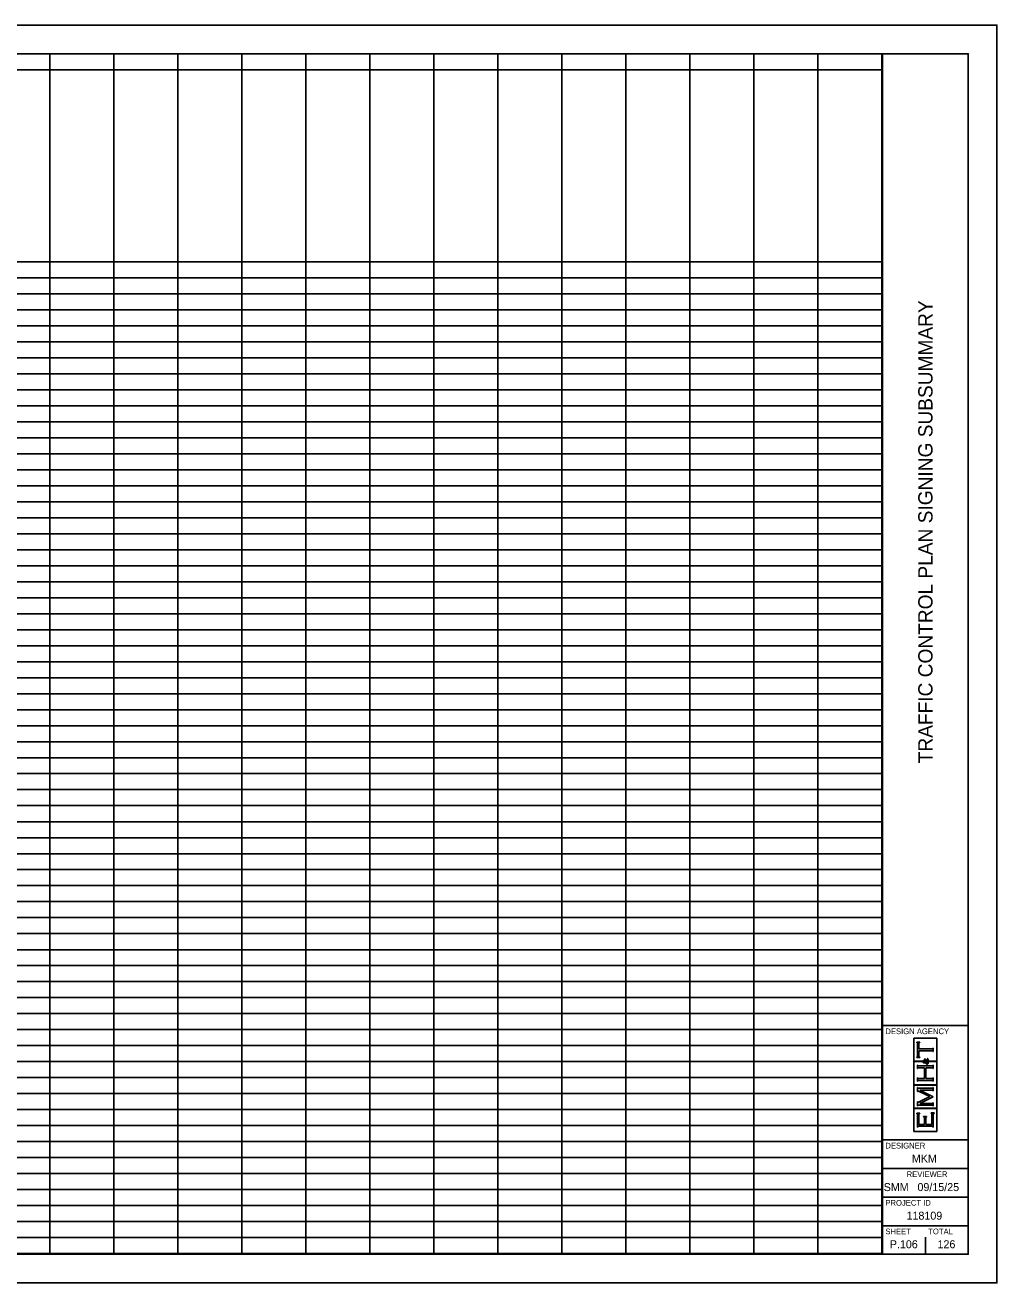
# Model space of a CAD drawing. Extents: x 0 to 34, y 0 to 22.
# Drawn here: x 17 to 34, y 0 to 22 of the extents above; entities that cross this region are included whole.
import ezdxf

# ---------------------------------------------------------------- set-up
doc = ezdxf.new("R2010")
doc.units = 0
for name, color, linetype in [('Default', 7, 'Continuous'), ('SH_Border', 7, 'Continuous'), ('SH_Cut_Line', 7, 'Continuous'), ('SH_Data', 7, 'Continuous')]:
    doc.layers.add(name, color=color, linetype=linetype)

msp = doc.modelspace()

# ---------------------------------------------------------------- linework, layer by layer
at = {"layer": 'Default'}
for p, q in [((1.5, 21.499), (31.985, 21.499)), ((17.434, 21.499), (17.434, 0.512)), ((18.553, 21.499), (18.553, 0.512)), ((19.673, 21.499), (19.673, 0.512)), ((20.792, 21.499), (20.792, 0.512)), ((21.911, 21.499), (21.911, 0.512)), ((23.031, 21.499), (23.031, 0.512)), ((24.15, 21.499), (24.15, 0.512)), ((25.269, 21.499), (25.269, 0.512)), ((26.389, 21.499), (26.389, 0.512)), ((27.508, 21.499), (27.508, 0.512)), ((28.627, 21.499), (28.627, 0.512)), ((29.747, 21.499), (29.747, 0.512)), ((30.866, 21.499), (30.866, 0.512)), ((31.985, 21.499), (31.985, 0.512)), ((10.718, 21.219), (31.985, 21.219)), ((10.718, 17.861), (31.985, 17.861)), ((1.5, 17.581), (31.985, 17.581)), ((1.5, 17.302), (31.985, 17.302)), ((1.5, 17.022), (31.985, 17.022)), ((1.5, 16.742), (31.985, 16.742)), ((1.5, 16.462), (31.985, 16.462)), ((1.5, 16.182), (31.985, 16.182)), ((1.5, 15.902), (31.985, 15.902)), ((1.5, 15.623), (31.985, 15.623)), ((1.5, 15.343), (31.985, 15.343)), ((1.5, 15.063), (31.985, 15.063)), ((1.5, 14.783), (31.985, 14.783)), ((1.5, 14.503), (31.985, 14.503)), ((1.5, 14.223), (31.985, 14.223)), ((1.5, 13.944), (31.985, 13.944)), ((1.5, 13.664), (31.985, 13.664)), ((1.5, 13.384), (31.985, 13.384)), ((1.5, 13.104), (31.985, 13.104)), ((1.5, 12.824), (31.985, 12.824)), ((1.5, 12.544), (31.985, 12.544)), ((1.5, 12.265), (31.985, 12.265)), ((1.5, 11.985), (31.985, 11.985)), ((1.5, 11.705), (31.985, 11.705)), ((1.5, 11.425), (31.985, 11.425)), ((1.5, 11.145), (31.985, 11.145)), ((1.5, 10.865), (31.985, 10.865)), ((1.5, 10.586), (31.985, 10.586)), ((1.5, 10.306), (31.985, 10.306)), ((1.5, 10.026), (31.985, 10.026)), ((1.5, 9.746), (31.985, 9.746)), ((1.5, 9.466), (31.985, 9.466)), ((1.5, 9.186), (31.985, 9.186)), ((1.5, 8.907), (31.985, 8.907)), ((1.5, 8.627), (31.985, 8.627)), ((1.5, 8.347), (31.985, 8.347)), ((1.5, 8.067), (31.985, 8.067)), ((1.5, 7.787), (31.985, 7.787)), ((1.5, 7.507), (31.985, 7.507)), ((1.5, 7.228), (31.985, 7.228)), ((1.5, 6.948), (31.985, 6.948)), ((1.5, 6.668), (31.985, 6.668)), ((1.5, 6.388), (31.985, 6.388)), ((1.5, 6.108), (31.985, 6.108)), ((1.5, 5.828), (31.985, 5.828)), ((1.5, 5.549), (31.985, 5.549)), ((1.5, 5.269), (31.985, 5.269)), ((1.5, 4.989), (31.985, 4.989)), ((1.5, 4.709), (31.985, 4.709)), ((1.5, 4.429), (31.985, 4.429)), ((1.5, 4.149), (31.985, 4.149)), ((1.5, 3.87), (31.985, 3.87)), ((1.5, 3.59), (31.985, 3.59)), ((1.5, 3.31), (31.985, 3.31)), ((1.5, 3.03), (31.985, 3.03)), ((1.5, 2.75), (31.985, 2.75)), ((1.5, 2.47), (31.985, 2.47)), ((1.5, 2.191), (31.985, 2.191)), ((1.5, 1.911), (31.985, 1.911)), ((1.5, 1.631), (31.985, 1.631)), ((1.5, 1.351), (31.985, 1.351)), ((1.5, 1.071), (31.985, 1.071)), ((1.5, 0.791), (31.985, 0.791)), ((1.5, 0.512), (31.985, 0.512))]:
    msp.add_line(p, q, dxfattribs=at)
at = {"layer": 'SH_Border'}
for p, q in [((32, 0.5), (32, 21.5)), ((32, 4.5), (33.5, 4.5)), ((32, 2.5), (33.5, 2.5)), ((32, 2), (33.5, 2)), ((32, 1.5), (33.5, 1.5)), ((32, 1), (33.5, 1))]:
    msp.add_line(p, q, dxfattribs=at)
msp.add_lwpolyline([(1.5, 21.5), (33.5, 21.5), (33.5, 0.5), (1.5, 0.5)], close=True, dxfattribs=at)
at = {"layer": 'SH_Cut_Line'}
msp.add_lwpolyline([(0, 0), (34, 0), (34, 22), (0, 22)], close=True, dxfattribs=at)
at = {"layer": 'SH_Data'}
for p, q in [((32.952, 4.279), (32.547, 4.279)), ((32.547, 4.279), (32.547, 3.875)), ((32.598, 4.204), (32.598, 4.211)), ((32.598, 4.211), (32.65, 4.211)), ((32.603, 4.203), (32.598, 4.204)), ((32.606, 4.201), (32.603, 4.203)), ((32.608, 4.199), (32.606, 4.201)), ((32.61, 4.196), (32.608, 4.199)), ((32.611, 4.192), (32.61, 4.196)), ((32.611, 4.187), (32.611, 4.192)), ((32.611, 3.968), (32.611, 4.187)), ((32.638, 4.196), (32.637, 4.192)), ((32.637, 4.192), (32.637, 4.187)), ((32.637, 4.187), (32.637, 4.093)), ((32.64, 4.199), (32.638, 4.196)), ((32.642, 4.201), (32.64, 4.199)), ((32.645, 4.203), (32.642, 4.201)), ((32.65, 4.204), (32.645, 4.203)), ((32.65, 4.211), (32.65, 4.204)), ((32.952, 3.875), (32.952, 4.279)), ((32.61, 3.958), (32.611, 3.962)), ((32.611, 3.962), (32.611, 3.968)), ((32.637, 4.093), (32.864, 4.093)), ((32.864, 4.061), (32.637, 4.061)), ((32.637, 4.061), (32.637, 3.968)), ((32.637, 3.968), (32.637, 3.962)), ((32.637, 3.962), (32.638, 3.958)), ((32.864, 4.093), (32.869, 4.093)), ((32.87, 4.061), (32.864, 4.061)), ((32.869, 4.093), (32.873, 4.094)), ((32.874, 4.06), (32.87, 4.061)), ((32.873, 4.094), (32.876, 4.096)), ((32.876, 4.059), (32.874, 4.06)), ((32.876, 4.096), (32.878, 4.097)), ((32.878, 4.057), (32.876, 4.059)), ((32.878, 4.097), (32.88, 4.101)), ((32.88, 4.053), (32.878, 4.057)), ((32.88, 4.101), (32.881, 4.106)), ((32.881, 4.048), (32.88, 4.053)), ((32.881, 4.106), (32.888, 4.106)), ((32.888, 4.048), (32.881, 4.048)), ((32.888, 4.106), (32.888, 4.048)), ((32.547, 3.875), (32.696, 3.875)), ((32.696, 3.869), (32.547, 3.869)), ((32.547, 3.869), (32.547, 3.465)), ((32.598, 3.95), (32.603, 3.951)), ((32.598, 3.944), (32.598, 3.95)), ((32.65, 3.944), (32.598, 3.944)), ((32.603, 3.951), (32.606, 3.953)), ((32.606, 3.953), (32.608, 3.955)), ((32.608, 3.955), (32.61, 3.958)), ((32.611, 3.749), (32.611, 3.807)), ((32.611, 3.807), (32.617, 3.807)), ((32.617, 3.749), (32.611, 3.749)), ((32.617, 3.807), (32.619, 3.802)), ((32.618, 3.754), (32.617, 3.749)), ((32.62, 3.758), (32.618, 3.754)), ((32.619, 3.802), (32.62, 3.798)), ((32.62, 3.798), (32.623, 3.797)), ((32.623, 3.76), (32.62, 3.758)), ((32.623, 3.797), (32.625, 3.795)), ((32.625, 3.761), (32.623, 3.76)), ((32.625, 3.795), (32.629, 3.794)), ((32.629, 3.762), (32.625, 3.761)), ((32.629, 3.794), (32.635, 3.794)), ((32.635, 3.762), (32.629, 3.762)), ((32.635, 3.794), (32.864, 3.794)), ((32.732, 3.762), (32.635, 3.762)), ((32.638, 3.958), (32.64, 3.955)), ((32.64, 3.955), (32.642, 3.953)), ((32.642, 3.953), (32.645, 3.951)), ((32.645, 3.951), (32.65, 3.95)), ((32.65, 3.95), (32.65, 3.944)), ((32.696, 3.875), (32.696, 3.869)), ((32.703, 3.879), (32.705, 3.883)), ((32.703, 3.873), (32.703, 3.879)), ((32.703, 3.868), (32.703, 3.873)), ((32.705, 3.863), (32.703, 3.868)), ((32.705, 3.883), (32.708, 3.887)), ((32.708, 3.858), (32.705, 3.863)), ((32.708, 3.887), (32.711, 3.89)), ((32.709, 3.879), (32.708, 3.876)), ((32.708, 3.876), (32.708, 3.873)), ((32.708, 3.873), (32.708, 3.869)), ((32.708, 3.869), (32.71, 3.866)), ((32.712, 3.853), (32.708, 3.858)), ((32.712, 3.881), (32.709, 3.879)), ((32.71, 3.866), (32.712, 3.864)), ((32.711, 3.89), (32.715, 3.892)), ((32.714, 3.883), (32.712, 3.881)), ((32.712, 3.864), (32.715, 3.862)), ((32.718, 3.85), (32.712, 3.853)), ((32.716, 3.884), (32.714, 3.883)), ((32.715, 3.892), (32.72, 3.892)), ((32.715, 3.862), (32.718, 3.861)), ((32.72, 3.884), (32.716, 3.884)), ((32.718, 3.861), (32.721, 3.861)), ((32.726, 3.85), (32.718, 3.85)), ((32.72, 3.892), (32.725, 3.892)), ((32.724, 3.884), (32.72, 3.884)), ((32.721, 3.861), (32.723, 3.861)), ((32.723, 3.861), (32.725, 3.862)), ((32.728, 3.882), (32.724, 3.884)), ((32.725, 3.892), (32.729, 3.89)), ((32.725, 3.862), (32.728, 3.862)), ((32.729, 3.85), (32.726, 3.85)), ((32.731, 3.88), (32.728, 3.882)), ((32.728, 3.862), (32.731, 3.863)), ((32.729, 3.89), (32.732, 3.887)), ((32.731, 3.85), (32.729, 3.85)), ((32.734, 3.877), (32.731, 3.88)), ((32.731, 3.863), (32.735, 3.865)), ((32.734, 3.851), (32.731, 3.85)), ((32.732, 3.887), (32.736, 3.883)), ((32.732, 3.572), (32.732, 3.762)), ((32.737, 3.872), (32.734, 3.877)), ((32.737, 3.852), (32.734, 3.851)), ((32.735, 3.865), (32.74, 3.867)), ((32.736, 3.883), (32.74, 3.878)), ((32.74, 3.867), (32.737, 3.872)), ((32.741, 3.853), (32.737, 3.852)), ((32.738, 3.893), (32.738, 3.922)), ((32.738, 3.922), (32.741, 3.922)), ((32.741, 3.893), (32.738, 3.893)), ((32.74, 3.878), (32.744, 3.869)), ((32.741, 3.922), (32.741, 3.918)), ((32.741, 3.918), (32.742, 3.915)), ((32.742, 3.896), (32.741, 3.895)), ((32.741, 3.895), (32.741, 3.893)), ((32.746, 3.855), (32.741, 3.853)), ((32.742, 3.915), (32.743, 3.913)), ((32.743, 3.897), (32.742, 3.896)), ((32.743, 3.913), (32.745, 3.911)), ((32.745, 3.899), (32.743, 3.897)), ((32.744, 3.869), (32.754, 3.875)), ((32.745, 3.911), (32.749, 3.908)), ((32.746, 3.899), (32.745, 3.899)), ((32.748, 3.899), (32.746, 3.899)), ((32.752, 3.844), (32.746, 3.855)), ((32.755, 3.899), (32.748, 3.899)), ((32.749, 3.908), (32.756, 3.904)), ((32.756, 3.86), (32.751, 3.857)), ((32.751, 3.857), (32.754, 3.852)), ((32.757, 3.837), (32.752, 3.844)), ((32.754, 3.875), (32.764, 3.881)), ((32.754, 3.852), (32.757, 3.848)), ((32.763, 3.895), (32.755, 3.899)), ((32.756, 3.904), (32.763, 3.9)), ((32.761, 3.863), (32.756, 3.86)), ((32.757, 3.848), (32.761, 3.845)), ((32.763, 3.833), (32.757, 3.837)), ((32.864, 3.762), (32.759, 3.762)), ((32.759, 3.762), (32.759, 3.572)), ((32.764, 3.865), (32.761, 3.863)), ((32.761, 3.845), (32.765, 3.843)), ((32.763, 3.9), (32.77, 3.896)), ((32.772, 3.887), (32.763, 3.895)), ((32.768, 3.829), (32.763, 3.833)), ((32.764, 3.881), (32.772, 3.887)), ((32.768, 3.867), (32.764, 3.865)), ((32.765, 3.843), (32.769, 3.841)), ((32.774, 3.872), (32.768, 3.867)), ((32.774, 3.827), (32.768, 3.829)), ((32.769, 3.841), (32.773, 3.841)), ((32.77, 3.896), (32.776, 3.891)), ((32.773, 3.841), (32.778, 3.841)), ((32.782, 3.878), (32.774, 3.872)), ((32.779, 3.827), (32.774, 3.827)), ((32.776, 3.891), (32.781, 3.895)), ((32.778, 3.841), (32.782, 3.843)), ((32.779, 3.923), (32.781, 3.926)), ((32.782, 3.922), (32.779, 3.923)), ((32.785, 3.827), (32.779, 3.827)), ((32.781, 3.926), (32.787, 3.924)), ((32.781, 3.895), (32.784, 3.898)), ((32.785, 3.921), (32.782, 3.922)), ((32.786, 3.873), (32.782, 3.878)), ((32.782, 3.843), (32.786, 3.846)), ((32.784, 3.898), (32.786, 3.901)), ((32.786, 3.919), (32.785, 3.921)), ((32.79, 3.829), (32.785, 3.827)), ((32.788, 3.917), (32.786, 3.919)), ((32.786, 3.901), (32.788, 3.904)), ((32.791, 3.886), (32.786, 3.881)), ((32.786, 3.881), (32.791, 3.876)), ((32.788, 3.869), (32.786, 3.873)), ((32.786, 3.846), (32.789, 3.849)), ((32.787, 3.924), (32.792, 3.921)), ((32.789, 3.914), (32.788, 3.917)), ((32.788, 3.904), (32.789, 3.908)), ((32.79, 3.867), (32.788, 3.869)), ((32.789, 3.911), (32.789, 3.914)), ((32.789, 3.908), (32.789, 3.911)), ((32.789, 3.849), (32.791, 3.853)), ((32.791, 3.864), (32.79, 3.867)), ((32.793, 3.834), (32.79, 3.829)), ((32.794, 3.89), (32.791, 3.886)), ((32.791, 3.876), (32.795, 3.87)), ((32.791, 3.861), (32.791, 3.864)), ((32.791, 3.859), (32.791, 3.861)), ((32.791, 3.853), (32.791, 3.859)), ((32.792, 3.921), (32.795, 3.918)), ((32.797, 3.838), (32.793, 3.834)), ((32.796, 3.894), (32.794, 3.89)), ((32.795, 3.918), (32.798, 3.914)), ((32.795, 3.87), (32.797, 3.866)), ((32.798, 3.897), (32.796, 3.894)), ((32.797, 3.866), (32.798, 3.861)), ((32.799, 3.844), (32.797, 3.838)), ((32.798, 3.914), (32.799, 3.91)), ((32.799, 3.901), (32.798, 3.897)), ((32.798, 3.861), (32.799, 3.857)), ((32.799, 3.91), (32.799, 3.905)), ((32.799, 3.905), (32.799, 3.901)), ((32.803, 3.869), (32.799, 3.875)), ((32.799, 3.875), (32.952, 3.875)), ((32.799, 3.857), (32.799, 3.852)), ((32.799, 3.852), (32.799, 3.844)), ((32.952, 3.869), (32.803, 3.869)), ((32.864, 3.794), (32.869, 3.794)), ((32.87, 3.762), (32.864, 3.762)), ((32.869, 3.794), (32.873, 3.795)), ((32.874, 3.761), (32.87, 3.762)), ((32.873, 3.795), (32.876, 3.797)), ((32.876, 3.76), (32.874, 3.761)), ((32.876, 3.797), (32.878, 3.798)), ((32.878, 3.758), (32.876, 3.76)), ((32.878, 3.798), (32.88, 3.802)), ((32.88, 3.754), (32.878, 3.758)), ((32.88, 3.802), (32.881, 3.807)), ((32.881, 3.749), (32.88, 3.754)), ((32.881, 3.807), (32.888, 3.807)), ((32.888, 3.749), (32.881, 3.749)), ((32.888, 3.807), (32.888, 3.749)), ((32.952, 3.465), (32.952, 3.869)), ((32.611, 3.527), (32.611, 3.585)), ((32.611, 3.585), (32.617, 3.585)), ((32.617, 3.527), (32.611, 3.527)), ((32.617, 3.585), (32.619, 3.58)), ((32.618, 3.532), (32.617, 3.527)), ((32.62, 3.536), (32.618, 3.532)), ((32.619, 3.58), (32.62, 3.576)), ((32.62, 3.576), (32.623, 3.574)), ((32.623, 3.537), (32.62, 3.536)), ((32.623, 3.574), (32.625, 3.573)), ((32.625, 3.539), (32.623, 3.537)), ((32.625, 3.573), (32.629, 3.572)), ((32.629, 3.54), (32.625, 3.539)), ((32.629, 3.572), (32.635, 3.572)), ((32.635, 3.54), (32.629, 3.54)), ((32.635, 3.572), (32.732, 3.572)), ((32.864, 3.54), (32.635, 3.54)), ((32.759, 3.572), (32.864, 3.572)), ((32.864, 3.572), (32.87, 3.572)), ((32.87, 3.54), (32.864, 3.54)), ((32.87, 3.572), (32.874, 3.573)), ((32.874, 3.539), (32.87, 3.54)), ((32.874, 3.573), (32.876, 3.574)), ((32.876, 3.538), (32.874, 3.539)), ((32.876, 3.574), (32.878, 3.576)), ((32.878, 3.536), (32.876, 3.538)), ((32.878, 3.576), (32.88, 3.58)), ((32.88, 3.532), (32.878, 3.536)), ((32.88, 3.58), (32.881, 3.585)), ((32.881, 3.527), (32.88, 3.532)), ((32.881, 3.585), (32.888, 3.585)), ((32.888, 3.527), (32.881, 3.527)), ((32.888, 3.585), (32.888, 3.527)), ((32.547, 3.465), (32.952, 3.465)), ((32.952, 3.459), (32.547, 3.459)), ((32.547, 3.459), (32.547, 3.055)), ((32.611, 3.345), (32.611, 3.418)), ((32.611, 3.418), (32.617, 3.418)), ((32.617, 3.345), (32.611, 3.345)), ((32.617, 3.418), (32.619, 3.412)), ((32.62, 3.352), (32.617, 3.345)), ((32.619, 3.412), (32.62, 3.409)), ((32.62, 3.409), (32.623, 3.407)), ((32.622, 3.355), (32.62, 3.352)), ((32.626, 3.355), (32.622, 3.355)), ((32.623, 3.407), (32.625, 3.405)), ((32.625, 3.405), (32.629, 3.405)), ((32.629, 3.355), (32.626, 3.355)), ((32.629, 3.405), (32.635, 3.405)), ((32.633, 3.353), (32.629, 3.355)), ((32.64, 3.35), (32.633, 3.353)), ((32.635, 3.405), (32.864, 3.405)), ((32.825, 3.257), (32.64, 3.35)), ((32.864, 3.373), (32.654, 3.373)), ((32.654, 3.373), (32.888, 3.255)), ((32.75, 3.5), (32.75, 3.5)), ((32.864, 3.405), (32.869, 3.405)), ((32.87, 3.373), (32.864, 3.373)), ((32.869, 3.405), (32.873, 3.405)), ((32.874, 3.372), (32.87, 3.373)), ((32.873, 3.405), (32.876, 3.407)), ((32.876, 3.37), (32.874, 3.372)), ((32.876, 3.407), (32.878, 3.409)), ((32.878, 3.369), (32.876, 3.37)), ((32.878, 3.409), (32.88, 3.412)), ((32.88, 3.365), (32.878, 3.369)), ((32.88, 3.412), (32.881, 3.418)), ((32.881, 3.36), (32.88, 3.365)), ((32.881, 3.418), (32.888, 3.418)), ((32.888, 3.36), (32.881, 3.36)), ((32.888, 3.418), (32.888, 3.36)), ((32.952, 3.055), (32.952, 3.459)), ((32.611, 3.096), (32.611, 3.168)), ((32.611, 3.168), (32.617, 3.168)), ((32.617, 3.096), (32.611, 3.096)), ((32.617, 3.168), (32.62, 3.162)), ((32.618, 3.102), (32.617, 3.096)), ((32.62, 3.105), (32.618, 3.102)), ((32.62, 3.162), (32.622, 3.158)), ((32.623, 3.107), (32.62, 3.105)), ((32.622, 3.158), (32.626, 3.158)), ((32.625, 3.109), (32.623, 3.107)), ((32.629, 3.109), (32.625, 3.109)), ((32.626, 3.158), (32.627, 3.158)), ((32.627, 3.158), (32.633, 3.161)), ((32.635, 3.109), (32.629, 3.109)), ((32.633, 3.161), (32.641, 3.165)), ((32.864, 3.109), (32.635, 3.109)), ((32.641, 3.165), (32.825, 3.257)), ((32.888, 3.255), (32.654, 3.138)), ((32.654, 3.138), (32.864, 3.138)), ((32.864, 3.138), (32.869, 3.138)), ((32.87, 3.109), (32.864, 3.109)), ((32.869, 3.138), (32.873, 3.139)), ((32.874, 3.109), (32.87, 3.109)), ((32.873, 3.139), (32.876, 3.141)), ((32.876, 3.107), (32.874, 3.109)), ((32.876, 3.141), (32.878, 3.143)), ((32.878, 3.105), (32.876, 3.107)), ((32.878, 3.143), (32.88, 3.146)), ((32.88, 3.102), (32.878, 3.105)), ((32.88, 3.146), (32.881, 3.151)), ((32.881, 3.096), (32.88, 3.102)), ((32.881, 3.151), (32.888, 3.151)), ((32.888, 3.096), (32.881, 3.096)), ((32.888, 3.151), (32.888, 3.096)), ((32.547, 3.055), (32.952, 3.055)), ((32.952, 3.049), (32.547, 3.049)), ((32.547, 3.049), (32.547, 2.645)), ((32.598, 2.962), (32.598, 2.969)), ((32.598, 2.969), (32.65, 2.969)), ((32.603, 2.961), (32.598, 2.962)), ((32.606, 2.959), (32.603, 2.961)), ((32.608, 2.957), (32.606, 2.959)), ((32.61, 2.955), (32.608, 2.957)), ((32.611, 2.951), (32.61, 2.955)), ((32.611, 2.945), (32.611, 2.951)), ((32.611, 2.725), (32.611, 2.945)), ((32.64, 2.957), (32.638, 2.955)), ((32.638, 2.955), (32.638, 2.951)), ((32.638, 2.951), (32.638, 2.945)), ((32.638, 2.945), (32.638, 2.77)), ((32.642, 2.959), (32.64, 2.957)), ((32.645, 2.961), (32.642, 2.959)), ((32.65, 2.962), (32.645, 2.961)), ((32.65, 2.969), (32.65, 2.962)), ((32.719, 2.902), (32.719, 2.908)), ((32.719, 2.908), (32.772, 2.908)), ((32.724, 2.901), (32.719, 2.902)), ((32.728, 2.899), (32.724, 2.901)), ((32.729, 2.896), (32.728, 2.899)), ((32.731, 2.894), (32.729, 2.896)), ((32.732, 2.89), (32.731, 2.894)), ((32.732, 2.884), (32.732, 2.89)), ((32.732, 2.77), (32.732, 2.884)), ((32.76, 2.894), (32.759, 2.89)), ((32.759, 2.89), (32.759, 2.884)), ((32.759, 2.884), (32.759, 2.77)), ((32.761, 2.896), (32.76, 2.894)), ((32.763, 2.899), (32.761, 2.896)), ((32.767, 2.901), (32.763, 2.899)), ((32.772, 2.902), (32.767, 2.901)), ((32.772, 2.908), (32.772, 2.902)), ((32.848, 2.965), (32.848, 2.972)), ((32.848, 2.972), (32.901, 2.972)), ((32.853, 2.964), (32.848, 2.965)), ((32.857, 2.962), (32.853, 2.964)), ((32.859, 2.96), (32.857, 2.962)), ((32.86, 2.958), (32.859, 2.96)), ((32.861, 2.953), (32.86, 2.958)), ((32.861, 2.948), (32.861, 2.953)), ((32.861, 2.77), (32.861, 2.948)), ((32.889, 2.957), (32.888, 2.953)), ((32.888, 2.953), (32.888, 2.948)), ((32.888, 2.948), (32.888, 2.725)), ((32.891, 2.96), (32.889, 2.957)), ((32.892, 2.962), (32.891, 2.96)), ((32.896, 2.964), (32.892, 2.962)), ((32.901, 2.965), (32.896, 2.964)), ((32.901, 2.972), (32.901, 2.965)), ((32.952, 2.645), (32.952, 3.049)), ((32.547, 2.645), (32.952, 2.645)), ((32.617, 2.725), (32.611, 2.725)), ((32.619, 2.73), (32.617, 2.725)), ((32.62, 2.734), (32.619, 2.73)), ((32.623, 2.735), (32.62, 2.734)), ((32.625, 2.737), (32.623, 2.735)), ((32.629, 2.738), (32.625, 2.737)), ((32.635, 2.738), (32.629, 2.738)), ((32.864, 2.738), (32.635, 2.738)), ((32.638, 2.77), (32.732, 2.77)), ((32.759, 2.77), (32.861, 2.77)), ((32.87, 2.738), (32.864, 2.738)), ((32.874, 2.737), (32.87, 2.738)), ((32.876, 2.735), (32.874, 2.737)), ((32.878, 2.734), (32.876, 2.735)), ((32.88, 2.73), (32.878, 2.734)), ((32.881, 2.725), (32.88, 2.73)), ((32.888, 2.725), (32.881, 2.725)), ((32.375, 0.675), (32.375, 0.675)), ((32.75, 0.5), (32.75, 0.8))]:
    msp.add_line(p, q, dxfattribs=at)

# ---------------------------------------------------------------- texts
msp.add_text('TRAFFIC CONTROL PLAN SIGNING SUBSUMMARY', height=0.25, rotation=90, dxfattribs=at).set_placement((32.875, 9.088))
for s, height, p in [('DESIGN AGENCY', 0.1, (32.05, 4.35)), ('DESIGNER', 0.1, (32.05, 2.35)), ('MKM', 0.14, (32.513, 2.105)), ('REVIEWER', 0.1, (32.422, 1.85)), ('SMM', 0.14, (32.02, 1.605)), ('09/15/25', 0.14, (32.611, 1.605)), ('PROJECT ID', 0.1, (32.05, 1.35)), ('118109', 0.14, (32.42, 1.105)), ('SHEET', 0.1, (32.05, 0.85)), ('TOTAL', 0.1, (32.8, 0.85)), ('P.106', 0.14, (32.127, 0.605)), ('126', 0.14, (32.962, 0.605))]:
    msp.add_text(s, height=height, dxfattribs=at).set_placement(p)

doc.saveas('drawing.dxf')
